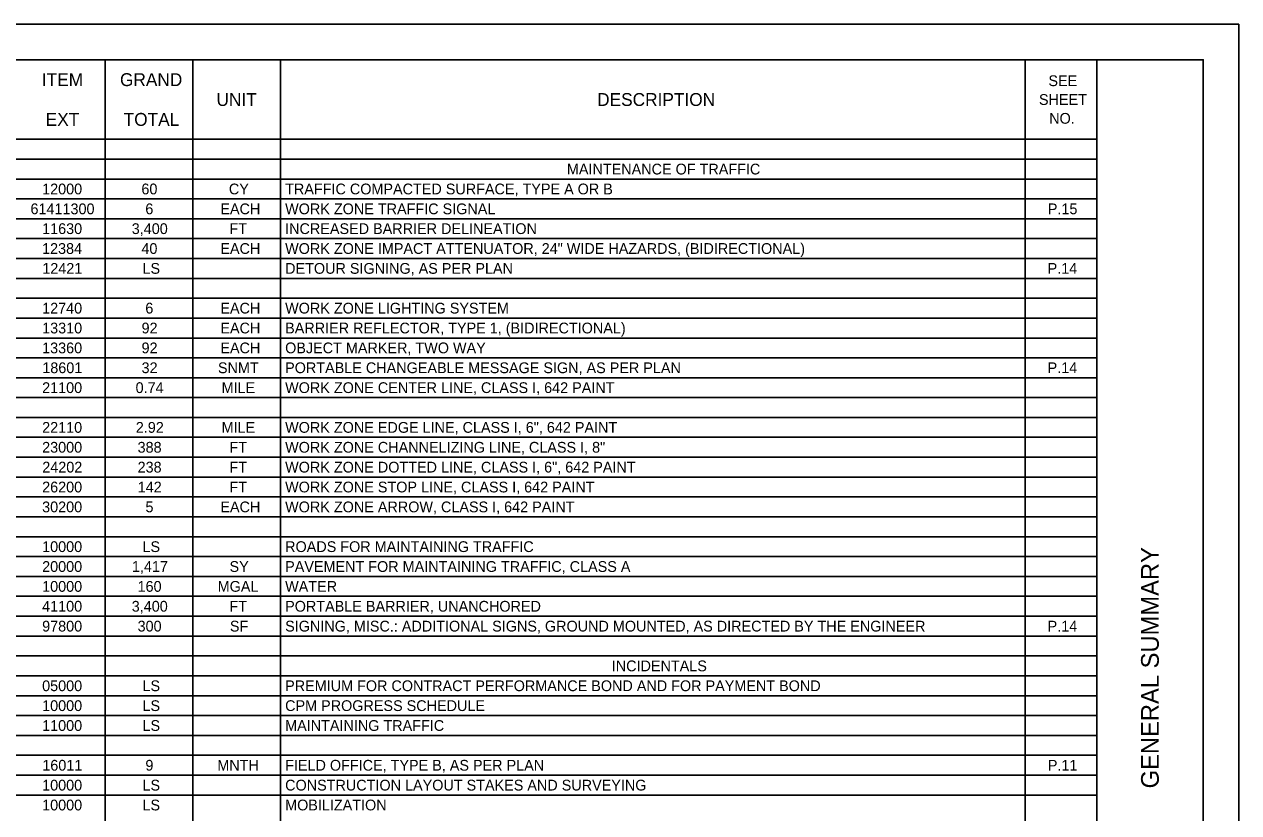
# Model space of a CAD drawing. Extents: x 0 to 34, y 0 to 22.
# Drawn here: x 16.9 to 34, y 10.89 to 22 of the extents above; entities that cross this region are included whole.
import ezdxf

# ---------------------------------------------------------------- set-up
doc = ezdxf.new("R2010")
doc.units = 0
for name, color, linetype in [('SH_Border', 7, 'Continuous'), ('SH_Cut_Line', 7, 'Continuous'), ('SH_Data', 7, 'Continuous'), ('SH_Text', 7, 'Continuous')]:
    doc.layers.add(name, color=color, linetype=linetype)

msp = doc.modelspace()

# ---------------------------------------------------------------- linework, layer by layer
at = {"layer": 'SH_Border'}
msp.add_line((32, 0.5), (32, 21.5), dxfattribs=at)
msp.add_lwpolyline([(1.5, 21.5), (33.5, 21.5), (33.5, 0.5), (1.5, 0.5)], close=True, dxfattribs=at)
at = {"layer": 'SH_Cut_Line'}
msp.add_lwpolyline([(0, 0), (34, 0), (34, 22), (0, 22)], close=True, dxfattribs=at)
at = {"layer": 'SH_Text'}
for p, q in [((1.5, 21.5), (32, 21.5)), ((18.035, 21.5), (18.035, 0.502)), ((19.27, 21.5), (19.27, 0.502)), ((20.505, 21.5), (20.505, 0.502)), ((30.995, 21.5), (30.995, 0.502)), ((32, 21.5), (32, 0.502)), ((1.5, 20.38), (32, 20.38)), ((1.5, 20.1), (32, 20.1)), ((1.5, 19.82), (32, 19.82)), ((1.5, 19.54), (32, 19.54)), ((1.5, 19.26), (32, 19.26)), ((1.5, 18.98), (32, 18.98)), ((1.5, 18.7), (32, 18.7)), ((1.5, 18.42), (32, 18.42)), ((1.5, 18.14), (32, 18.14)), ((1.5, 17.86), (32, 17.86)), ((1.5, 17.58), (32, 17.58)), ((1.5, 17.3), (32, 17.3)), ((1.5, 17.021), (32, 17.021)), ((1.5, 16.741), (32, 16.741)), ((1.5, 16.461), (32, 16.461)), ((1.5, 16.181), (32, 16.181)), ((1.5, 15.901), (32, 15.901)), ((1.5, 15.621), (32, 15.621)), ((1.5, 15.341), (32, 15.341)), ((1.5, 15.061), (32, 15.061)), ((1.5, 14.781), (32, 14.781)), ((1.5, 14.501), (32, 14.501)), ((1.5, 14.221), (32, 14.221)), ((1.5, 13.941), (32, 13.941)), ((1.5, 13.661), (32, 13.661)), ((1.5, 13.381), (32, 13.381)), ((1.5, 13.101), (32, 13.101)), ((1.5, 12.821), (32, 12.821)), ((1.5, 12.541), (32, 12.541)), ((1.5, 12.261), (32, 12.261)), ((1.5, 11.981), (32, 11.981)), ((1.5, 11.701), (32, 11.701)), ((1.5, 11.421), (32, 11.421)), ((1.5, 11.141), (32, 11.141))]:
    msp.add_line(p, q, dxfattribs=at)

# ---------------------------------------------------------------- texts
at = {"layer": 'SH_Data'}
msp.add_text('GENERAL SUMMARY', height=0.25, rotation=90, dxfattribs=at).set_placement((32.875, 11.235))
at = {"layer": 'SH_Text'}
for s, height, p in [('ITEM', 0.1818, (17.145, 21.129)), ('GRAND', 0.1818, (18.245, 21.129)), ('SEE ', 0.1515, (31.32, 21.129)), ('UNIT', 0.1818, (19.604, 20.849)), ('DESCRIPTION', 0.18181, (24.965, 20.849)), ('SHEET ', 0.1515, (31.187, 20.864)), ('EXT', 0.1818, (17.199, 20.569)), ('TOTAL', 0.1818, (18.297, 20.569)), ('NO.', 0.1515, (31.331, 20.599)), ('MAINTENANCE OF TRAFFIC', 0.15151, (24.539, 19.884)), ('12000', 0.1515, (17.149, 19.604)), ('60', 0.1515, (18.547, 19.604)), ('CY', 0.1515, (19.779, 19.604)), ('TRAFFIC COMPACTED SURFACE, TYPE A OR B', 0.15151, (20.571, 19.604)), ('61411300', 0.1515, (16.985, 19.324)), ('6', 0.152, (18.602, 19.324)), ('EACH', 0.1515, (19.659, 19.324)), ('WORK ZONE TRAFFIC SIGNAL', 0.15151, (20.571, 19.324)), ('P.15', 0.1515, (31.312, 19.324)), ('11630', 0.1515, (17.149, 19.045)), ('3,400', 0.1515, (18.411, 19.045)), ('FT', 0.1515, (19.786, 19.045)), ('INCREASED BARRIER DELINEATION', 0.15151, (20.571, 19.045)), ('12384', 0.1515, (17.148, 18.765)), ('40', 0.1515, (18.547, 18.765)), ('EACH', 0.1515, (19.659, 18.765)), ('WORK ZONE IMPACT ATTENUATOR, 24" WIDE HAZARDS, (BIDIRECTIONAL)', 0.15151, (20.571, 18.765)), ('12421', 0.1515, (17.151, 18.485)), ('LS', 0.1515, (18.562, 18.485)), ('DETOUR SIGNING, AS PER PLAN', 0.15151, (20.571, 18.485)), ('P.14', 0.1515, (31.309, 18.485)), ('12740', 0.1515, (17.149, 17.925)), ('6', 0.152, (18.602, 17.925)), ('EACH', 0.1515, (19.659, 17.925)), ('WORK ZONE LIGHTING SYSTEM', 0.15151, (20.571, 17.925)), ('13310', 0.1515, (17.149, 17.645)), ('92', 0.1515, (18.549, 17.645)), ('EACH', 0.1515, (19.659, 17.645)), ('BARRIER REFLECTOR, TYPE 1, (BIDIRECTIONAL)', 0.15151, (20.571, 17.645)), ('13360', 0.1515, (17.149, 17.365)), ('92', 0.1515, (18.549, 17.365)), ('EACH', 0.1515, (19.659, 17.365)), ('OBJECT MARKER, TWO WAY', 0.15151, (20.571, 17.365)), ('18601', 0.1515, (17.151, 17.085)), ('32', 0.1515, (18.549, 17.085)), ('SNMT', 0.1515, (19.625, 17.085)), ('PORTABLE CHANGEABLE MESSAGE SIGN, AS PER PLAN', 0.15151, (20.571, 17.085)), ('P.14', 0.1515, (31.309, 17.085)), ('21100', 0.1515, (17.149, 16.805)), ('0.74', 0.1515, (18.465, 16.805)), ('MILE', 0.1515, (19.676, 16.805)), ('WORK ZONE CENTER LINE, CLASS I, 642 PAINT', 0.15151, (20.571, 16.805)), ('22110', 0.1515, (17.149, 16.245)), ('2.92', 0.1515, (18.468, 16.245)), ('MILE', 0.1515, (19.676, 16.245)), ('WORK ZONE EDGE LINE, CLASS I, 6", 642 PAINT', 0.15151, (20.571, 16.245)), ('23000', 0.1515, (17.149, 15.965)), ('388', 0.1515, (18.493, 15.965)), ('FT', 0.1515, (19.786, 15.965)), ('WORK ZONE CHANNELIZING LINE, CLASS I, 8"', 0.15151, (20.571, 15.965)), ('24202', 0.1515, (17.151, 15.685)), ('238', 0.1515, (18.493, 15.685)), ('FT', 0.1515, (19.786, 15.685)), ('WORK ZONE DOTTED LINE, CLASS I, 6", 642 PAINT', 0.15151, (20.571, 15.685)), ('26200', 0.1515, (17.149, 15.405)), ('142', 0.1515, (18.495, 15.405)), ('FT', 0.1515, (19.786, 15.405)), ('WORK ZONE STOP LINE, CLASS I, 642 PAINT', 0.15151, (20.571, 15.405)), ('30200', 0.1515, (17.149, 15.125)), ('5', 0.152, (18.604, 15.125)), ('EACH', 0.1515, (19.659, 15.125)), ('WORK ZONE ARROW, CLASS I, 642 PAINT', 0.15151, (20.571, 15.125)), ('10000', 0.1515, (17.149, 14.565)), ('LS', 0.1515, (18.562, 14.565)), ('ROADS FOR MAINTAINING TRAFFIC', 0.15151, (20.571, 14.565)), ('20000', 0.1515, (17.149, 14.285)), ('1,417', 0.1515, (18.413, 14.285)), ('SY', 0.1515, (19.788, 14.285)), ('PAVEMENT FOR MAINTAINING TRAFFIC, CLASS A', 0.15151, (20.571, 14.285)), ('10000', 0.1515, (17.149, 14.005)), ('160', 0.1515, (18.493, 14.005)), ('MGAL', 0.1515, (19.621, 14.005)), ('WATER', 0.1515, (20.571, 14.005)), ('41100', 0.1515, (17.149, 13.725)), ('3,400', 0.1515, (18.411, 13.725)), ('FT', 0.1515, (19.786, 13.725)), ('PORTABLE BARRIER, UNANCHORED', 0.15151, (20.571, 13.725)), ('97800', 0.1515, (17.149, 13.445)), ('300', 0.1515, (18.493, 13.445)), ('SF', 0.1515, (19.793, 13.445)), ('SIGNING, MISC.: ADDITIONAL SIGNS, GROUND MOUNTED, AS DIRECTED BY THE ENGINEER', 0.15151, (20.571, 13.445)), ('P.14', 0.1515, (31.309, 13.445)), ('INCIDENTALS', 0.15151, (25.171, 12.885)), ('05000', 0.1515, (17.149, 12.605)), ('LS', 0.1515, (18.562, 12.605)), ('PREMIUM FOR CONTRACT PERFORMANCE BOND AND FOR PAYMENT BOND', 0.15151, (20.571, 12.605)), ('10000', 0.1515, (17.149, 12.325)), ('LS', 0.1515, (18.562, 12.325)), ('CPM PROGRESS SCHEDULE', 0.15151, (20.571, 12.325)), ('11000', 0.1515, (17.149, 12.045)), ('LS', 0.1515, (18.562, 12.045)), ('MAINTAINING TRAFFIC', 0.15151, (20.571, 12.045)), ('16011', 0.1515, (17.151, 11.485)), ('9', 0.152, (18.603, 11.485)), ('MNTH', 0.1515, (19.616, 11.485)), ('FIELD OFFICE, TYPE B, AS PER PLAN', 0.15151, (20.571, 11.485)), ('P.11', 0.1515, (31.312, 11.485)), ('10000', 0.1515, (17.149, 11.205)), ('LS', 0.1515, (18.562, 11.205)), ('CONSTRUCTION LAYOUT STAKES AND SURVEYING', 0.15151, (20.571, 11.205)), ('10000', 0.1515, (17.149, 10.925)), ('LS', 0.1515, (18.562, 10.925)), ('MOBILIZATION', 0.15151, (20.571, 10.925))]:
    msp.add_text(s, height=height, dxfattribs=at).set_placement(p)

doc.saveas('drawing.dxf')
